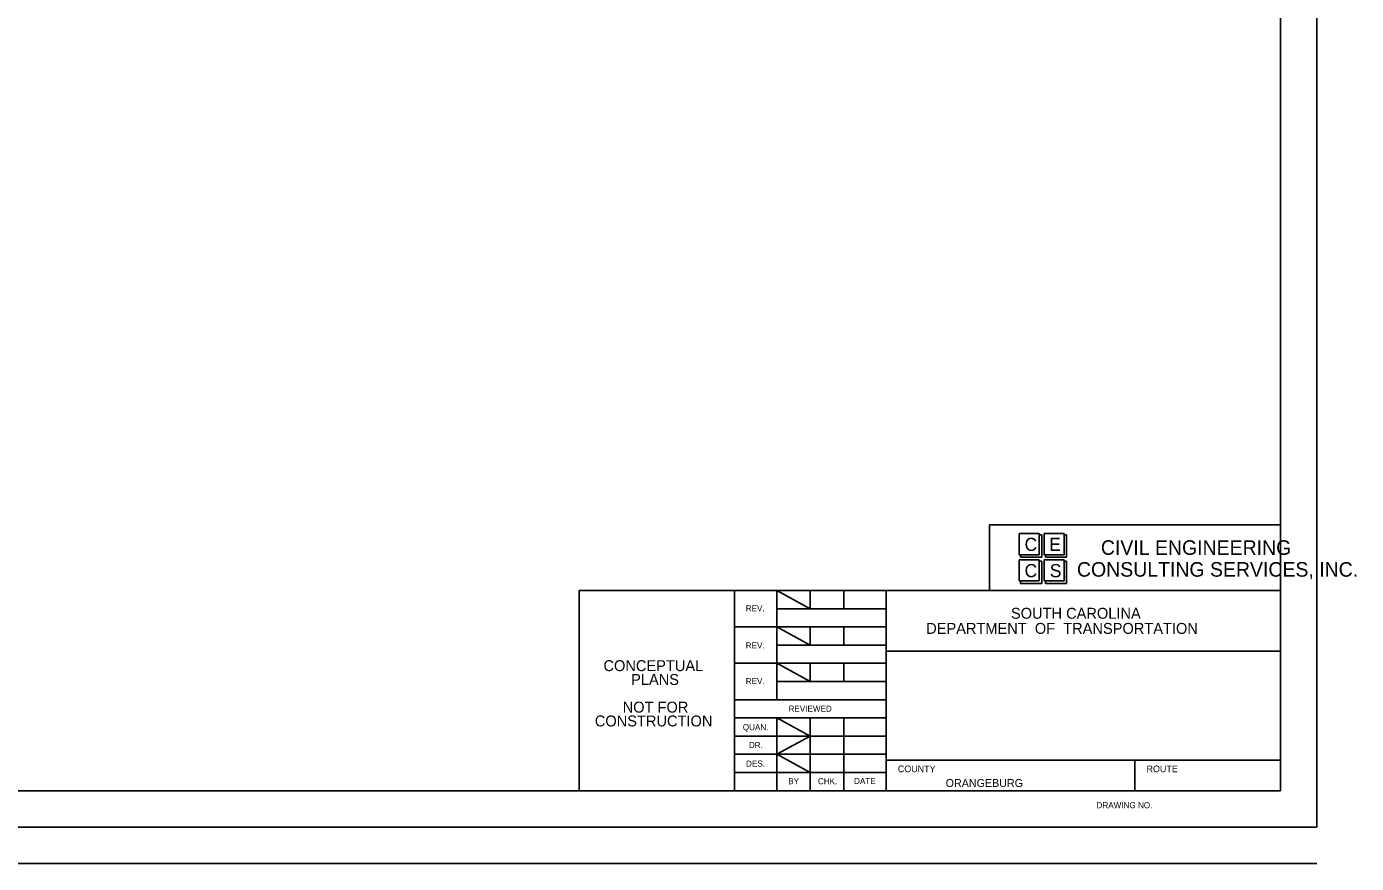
# Model space of a CAD drawing. Extents: x 0 to 36.5, y -0.5 to 22.5.
# Drawn here: x 18.27 to 36.54, y -0.5 to 11 of the extents above; entities that cross this region are included whole.
import ezdxf

# ---------------------------------------------------------------- set-up
doc = ezdxf.new("R2010")
doc.units = 0
for name, color, linetype in [('Level 1', 7, 'Continuous'), ('Level 2', 7, 'Continuous'), ('Level 3', 7, 'Continuous'), ('Level 4', 7, 'Continuous'), ('Level 63', 7, 'Continuous'), ('Level 7', 7, 'Continuous')]:
    doc.layers.add(name, color=color, linetype=linetype)

msp = doc.modelspace()

# ---------------------------------------------------------------- linework, layer by layer
at = {"layer": 'Level 1'}
for p, q in [((36, 0), (0.8, 0.001)), ((36, 0), (36, 0)), ((36, -0.5), (0.8, -0.499))]:
    msp.add_line(p, q, dxfattribs=at)
msp.add_lwpolyline([(1.5, 21.5), (35.5, 21.5), (35.5, 0.5), (1.5, 0.5)], close=True, dxfattribs=at)
at = {"layer": 'Level 2'}
for p, q in [((31.502, 4.155), (35.498, 4.155)), ((31.502, 3.25), (31.502, 4.155)), ((28, 3.25), (25.866, 3.25)), ((25.866, 3.25), (25.866, 0.5)), ((28, 3.25), (35.5, 3.25)), ((28, 0.5), (28, 3.25)), ((28.583, 3.25), (28.583, 1.75)), ((29.041, 3), (29.041, 3.25)), ((29.5, 3), (29.5, 3.25)), ((30.083, 0.5), (30.083, 3.25)), ((28.583, 3), (30.083, 3)), ((28, 2.75), (30.083, 2.75)), ((29.041, 2.5), (29.041, 2.75)), ((29.5, 2.5), (29.5, 2.75)), ((28.583, 2.5), (30.083, 2.5)), ((30.083, 2.417), (35.5, 2.417)), ((28, 2.25), (30.083, 2.25)), ((29.041, 2), (29.041, 2.25)), ((29.5, 2), (29.5, 2.25)), ((28.583, 2), (30.083, 2)), ((28, 1.75), (30.083, 1.75)), ((28, 1.5), (30.083, 1.5)), ((28.583, 1.5), (28.583, 0.5)), ((29.041, 1.5), (29.041, 0.5)), ((29.5, 1.5), (29.5, 0.5)), ((28, 1.25), (30.083, 1.25)), ((28, 1), (30.083, 1)), ((30.083, 0.917), (35.5, 0.917)), ((33.5, 0.5), (33.5, 0.917)), ((28, 0.75), (30.083, 0.75))]:
    msp.add_line(p, q, dxfattribs=at)
at = {"layer": 'Level 3'}
for p, q in [((28.583, 3.25), (29.041, 3)), ((28.583, 2.75), (29.041, 2.5)), ((28.583, 2.25), (29.041, 2)), ((28.583, 1.5), (29.041, 1.25)), ((29.041, 1.25), (28.583, 1)), ((28.583, 1), (29.041, 0.75))]:
    msp.add_line(p, q, dxfattribs=at)
at = {"layer": 'Level 63'}
msp.add_lwpolyline([(0, 22), (36, 22), (36, 0), (0, 0)], close=True, dxfattribs=at)
at = {"layer": 'Level 7'}
for p, q in [((32.186, 4.032), (31.912, 4.032)), ((31.912, 4.032), (31.912, 3.743)), ((32.186, 3.743), (32.186, 4.032)), ((32.186, 4.032), (32.186, 3.743)), ((32.528, 4.032), (32.254, 4.032)), ((32.254, 4.032), (32.254, 3.743)), ((32.528, 3.743), (32.528, 4.032)), ((32.528, 4.032), (32.528, 3.743)), ((32.22, 4.014), (32.186, 4.014)), ((32.22, 3.707), (32.22, 4.014)), ((32.562, 4.014), (32.528, 4.014)), ((32.562, 3.707), (32.562, 4.014)), ((31.912, 3.743), (32.186, 3.743)), ((32.186, 3.671), (31.912, 3.671)), ((31.912, 3.671), (31.912, 3.382)), ((32.186, 3.743), (31.929, 3.743)), ((31.929, 3.743), (31.929, 3.707)), ((31.929, 3.707), (32.22, 3.707)), ((32.186, 3.382), (32.186, 3.671)), ((32.186, 3.671), (32.186, 3.382)), ((32.254, 3.743), (32.528, 3.743)), ((32.528, 3.671), (32.254, 3.671)), ((32.254, 3.671), (32.254, 3.382)), ((32.528, 3.743), (32.271, 3.743)), ((32.271, 3.743), (32.271, 3.707)), ((32.271, 3.707), (32.562, 3.707)), ((32.528, 3.382), (32.528, 3.671)), ((32.528, 3.671), (32.528, 3.382)), ((32.22, 3.653), (32.186, 3.653)), ((32.22, 3.346), (32.22, 3.653)), ((32.562, 3.653), (32.528, 3.653)), ((32.562, 3.346), (32.562, 3.653)), ((31.912, 3.382), (32.186, 3.382)), ((32.186, 3.382), (31.929, 3.382)), ((31.929, 3.382), (31.929, 3.346)), ((31.929, 3.346), (32.22, 3.346)), ((32.254, 3.382), (32.528, 3.382)), ((32.528, 3.382), (32.271, 3.382)), ((32.271, 3.382), (32.271, 3.346)), ((32.271, 3.346), (32.562, 3.346))]:
    msp.add_line(p, q, dxfattribs=at)

# ---------------------------------------------------------------- texts
at = {"layer": 'Level 2'}
for s, p in [('REV.', (28.154, 2.964)), ('REV.', (28.154, 2.454)), ('REV.', (28.154, 1.964)), ('REVIEWED', (28.742, 1.584)), ('QUAN.', (28.113, 1.331)), ('DR.', (28.197, 1.086)), ('DES.', (28.158, 0.831)), ('BY', (28.737, 0.589)), ('CHK.', (29.146, 0.588)), ('DATE', (29.642, 0.592))]:
    msp.add_text(s, height=0.0833, dxfattribs=at).set_placement(p)
at = {"layer": 'Level 3'}
for s, height, p in [('COUNTY', 0.0917, (30.244, 0.754)), ('ROUTE', 0.0917, (33.661, 0.754)), ('ORANGEBURG', 0.11, (30.901, 0.55)), ('DRAWING NO.', 0.08333, (32.974, 0.259))]:
    msp.add_text(s, height=height, dxfattribs=at).set_placement(p)
at = {"layer": 'Level 4'}
for s, p in [('SOUTH CAROLINA', (31.798, 2.863)), ('DEPARTMENT  OF  TRANSPORTATION', (30.633, 2.655)), ('CONCEPTUAL', (26.199, 2.143)), ('PLANS', (26.579, 1.953)), ('NOT FOR', (26.463, 1.573)), ('CONSTRUCTION', (26.08, 1.383))]:
    msp.add_text(s, height=0.15, dxfattribs=at).set_placement(p)
at = {"layer": 'Level 7'}
for s, height, p in [('C', 0.18, (31.985, 3.795)), ('E', 0.18, (32.323, 3.795)), ('CIVIL ENGINEERING', 0.2, (33.034, 3.741)), ('C', 0.18, (31.985, 3.434)), ('S', 0.18, (32.331, 3.434)), ('CONSULTING SERVICES, INC.', 0.2, (32.705, 3.441))]:
    msp.add_text(s, height=height, dxfattribs=at).set_placement(p)

doc.saveas('drawing.dxf')
